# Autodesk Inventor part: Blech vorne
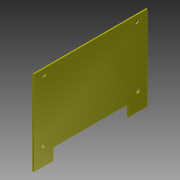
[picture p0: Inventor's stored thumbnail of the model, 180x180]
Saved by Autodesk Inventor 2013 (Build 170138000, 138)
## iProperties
Created: 2012-10
Part Number: Blech vorne
Material: Aluminium 6061
Document SubType Name: Modeling
Designer: Marvin
Density: 2.71 g/cm^3
Mass: 17.4162 g
Surface Area: 134.56 cm^2
Volume: 6.42664 cm^3
Author: Marvin
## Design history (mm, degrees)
sketch "Skizze1"
  geometry: L1 (-49.15, 73)-(-49.15, 0); L2 (-49.15, 0)-(-32.5, 0); L3 (-32.5, 0)-(-32.5, 10); L4 (-32.5, 10)-(32.5, 10); L5 (32.5, 10)-(32.5, 0); L6 (32.5, 0)-(49.15, 0); L7 (49.15, 0)-(49.15, 73); L8 (0, 9.353)-(0, -15.158); L9 (-49.15, 73)-(49.15, 73); L10 (-68.81, 0)-(68.81, 0) reference; 1 further point
  constraints: 18 end point, 5 parallel, 3 collinear, 1 perpendicular, 1 point on line, 1 vertical, 2 other
  dimensions: "d2" = 10 distance of L4.end L5.end; "d3" = 65 distance of L3.end L4.end; "d5" = 98.3 distance between parallel lines of L7 L1; "d45" = 73 distance between parallel lines of L2 L9
extrude "Extrusion1" new body sketch "Skizze1" distance "d14" = 1; taper "d15" = 0 deg
workplane "Arbeitsebene1"
workplane "Arbeitsebene2"
sketch "Skizze5"
  geometry: L1 (-87.6, 0)-(14.6, 0) reference; L2 (-73, 49.15)-(-73, -49.15) reference; 7 further points
  constraints: 2 symmetric about line
  dimensions: "d33" = 80 distance of point (-68, 40) point (-68, -40); "d35" = 82 distance of point (-15.5, 41) point (-15.5, -41); "d46" = 52.5 horizontal distance of point (-15.5, 41) point (-68, 40); "d47" = 5 distance from line of L2 point (-68, 40)
hole "Bohrung2" sketch "Skizze5" at (-68, -40), (-68, 40), (-15.5, 41), (-15.5, -41) diameter "d38" = 3.4; stored, may be unused: countersink angle "d42" = 90 deg, drill point angle "d44" = 118 deg; dims "d39" = 6, "d40" = 4, "d41" = 2, "d43" = 8
node "Volumenkörper1"
